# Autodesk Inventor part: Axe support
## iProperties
Shininess: 20.0
Angle Display Precision: 2
Document Length Units: 11269
Document Angle Units: 11279
Document Time Units: 11290
Document Mass Units: 11283
Document Length Units Precision: 3
Document Angle Units Precision: 2
Created: 2002-09
Part Number: Axe support
Material: Par défaut
Document SubType Name: Modélisation
Designer: administrateur
Density: 0.0
Volumn: 0.0
Area: 0.0
PropertySet Name: Model Information
Control State: 0
Master: False
Checked Out: False
Author: administrateur
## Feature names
1. Révolution1 [Revolution]
2. Extrusion1
3. Extrusion3
4. Symétrie1 [Mirror]
5. Extrusion5
6. Chanfrein2 [Chamfer]
7. Extrusion6
8. Symétrie3 [Mirror]
